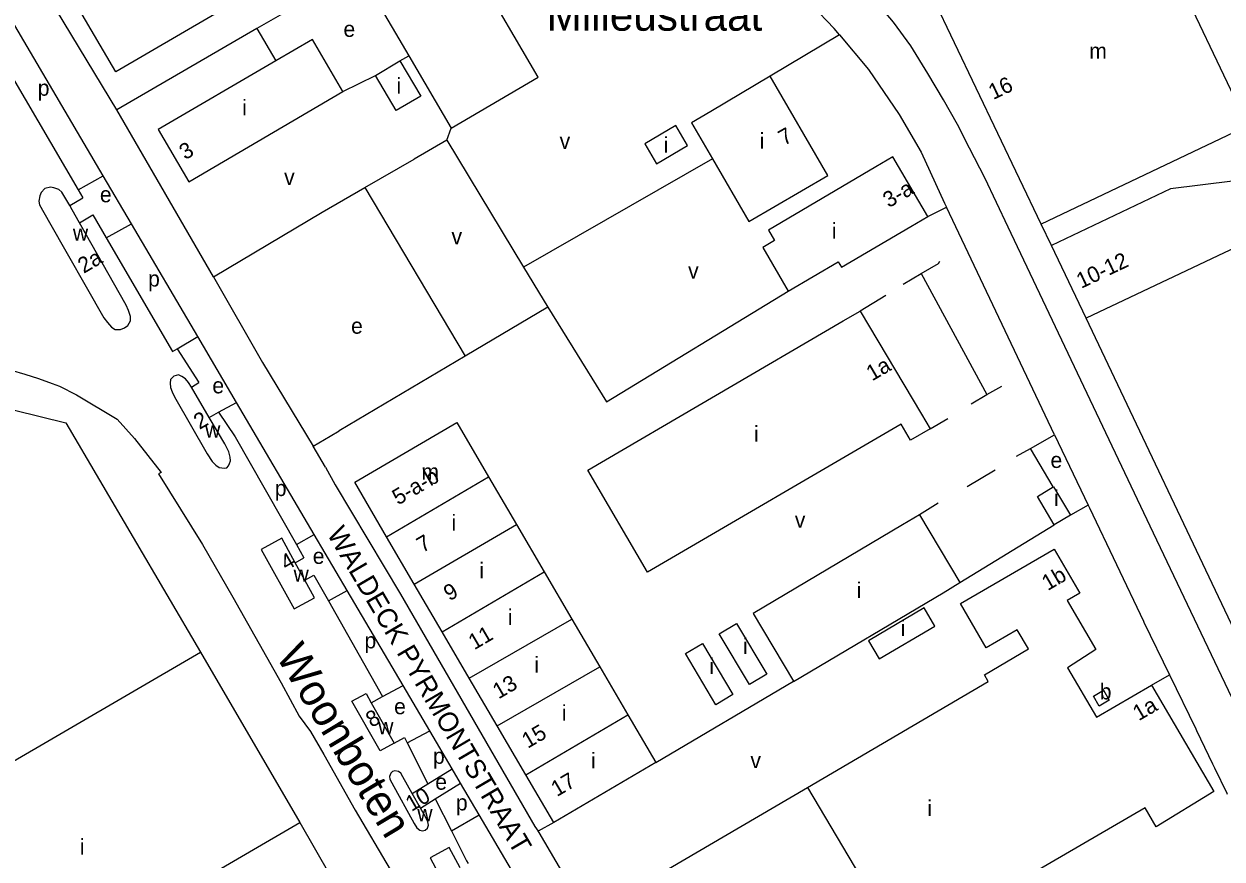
# Model space of a CAD drawing. Extents: x 157699 to 159683, y 381451 to 383293.
# Drawn here: x 159121.6 to 159425.3, y 382524.8 to 382736.7 of the extents above; entities that cross this region are included whole.
import ezdxf

# ---------------------------------------------------------------- set-up
doc = ezdxf.new("R2010")
doc.units = 0
for name, color, linetype in [('BLT_Basislijn', 7, 'Continuous'), ('BLT_Bebouwing', 7, 'Continuous'), ('BLT_Bebouwing_beschrifting', 7, 'Continuous'), ('BLT_Centroide', 7, 'Continuous'), ('BLT_Huisnummer', 7, 'Continuous'), ('BLT_Huisnummer_reeks', 7, 'Continuous'), ('BLT_Onderverdeling_panden', 7, 'Continuous'), ('BLT_Straatnaam', 7, 'Continuous')]:
    doc.layers.add(name, color=color, linetype=linetype)

msp = doc.modelspace()

# ---------------------------------------------------------------- linework, layer by layer
at = {"layer": 'BLT_Basislijn'}
for p, q in [((159081.87, 382786.07), (159135.33, 382694.59)), ((159145.12, 382714.94), (159124.62, 382748.97)), ((159189.49, 382740.66), (159180.65, 382735.54)), ((159180.65, 382735.54), (159145.12, 382714.94)), ((159180.65, 382735.54), (159185.44, 382727.36)), ((159328.36, 382733.92), (159310.76, 382723.44)), ((159216.91, 382727.32), (159219.18, 382728.66)), ((159202.47, 382719.59), (159210.72, 382723.67)), ((159169.62, 382672.57), (159145.12, 382714.94)), ((159228.78, 382707.2), (159229.92, 382710.31)), ((159228.78, 382707.2), (159220.49, 382702.38)), ((159228.78, 382707.2), (159248.23, 382675.04)), ((159208.03, 382695.22), (159220.49, 382702.38)), ((159296.17, 382702.5), (159248.23, 382675.04)), ((159135.33, 382694.59), (159141.7, 382698.15)), ((159135.33, 382694.59), (159136.5, 382692.58)), ((159208.03, 382695.22), (159233.46, 382652.44)), ((159133.19, 382690.63), (159136.5, 382692.58)), ((159350.78, 382687.89), (159355.44, 382690.22)), ((159382.84, 382632.46), (159355.44, 382690.22)), ((159135.67, 382686.29), (159139.02, 382688.26)), ((159139.02, 382688.26), (159142.41, 382682.47)), ((159142.41, 382682.47), (159148.85, 382686)), ((159407.09, 382609.31), (159371.1, 382685.16)), ((159382.07, 382680.52), (159379.52, 382685.92)), ((159142.41, 382682.47), (159159.29, 382653.57)), ((159344.49, 382670.67), (159349.05, 382673.36)), ((159349.05, 382673.36), (159365.71, 382642.67)), ((159340.07, 382667.79), (159333.58, 382663.87)), ((159254.41, 382664.87), (159233.46, 382652.44)), ((159430.88, 382577.83), (159390.88, 382662.04)), ((159160.47, 382654.28), (159165.68, 382657.38)), ((159233.46, 382652.44), (159201.5, 382633.47)), ((159164.08, 382644.56), (159165.89, 382645.71)), ((159365.71, 382642.67), (159369.52, 382644.84)), ((159361.74, 382640.32), (159365.71, 382642.67)), ((159170.95, 382638.2), (159175.49, 382640.69)), ((159168.57, 382636.89), (159170.95, 382638.2)), ((159351.34, 382634.01), (159355.81, 382636.61)), ((159376.77, 382628.98), (159382.84, 382632.46)), ((159382.84, 382632.46), (159391.39, 382614.65)), ((159198.02, 382624.28), (159194.91, 382629.63)), ((159373.21, 382627.02), (159376.77, 382628.98)), ((159382.53, 382619.23), (159376.77, 382628.98)), ((159367.86, 382623.52), (159360.69, 382619.31)), ((159353.39, 382615.09), (159348.65, 382612.2)), ((159391.39, 382614.65), (159386.91, 382612.05)), ((159358.9, 382594.96), (159382.81, 382609.61)), ((159434.7, 382551.26), (159407.09, 382609.31)), ((159190.65, 382604.66), (159195.2, 382607.16)), ((159190.38, 382600), (159192.59, 382601.24)), ((159192.8, 382595.62), (159195.06, 382596.89)), ((159198.77, 382590.34), (159203.55, 382592.97)), ((159405.51, 382584.93), (159412.02, 382571.56)), ((159407.48, 382568.92), (159412.02, 382571.56)), ((159412.02, 382571.56), (159418.71, 382557.83)), ((159212.52, 382566.06), (159217.7, 382568.9)), ((159281.8, 382549.29), (159316.66, 382570)), ((159209.66, 382564.48), (159212.52, 382566.06)), ((159218.78, 382554.28), (159224.46, 382557.4)), ((159215.45, 382554.21), (159218.07, 382555.68)), ((159223.98, 382543.9), (159230.16, 382547.7)), ((159225.86, 382540.15), (159232.28, 382544.1)), ((159220.02, 382541.5), (159223.98, 382543.9)), ((159222.13, 382537.75), (159220.02, 382541.5)), ((159222.13, 382537.75), (159225.86, 382540.15)), ((159229.98, 382531.95), (159237.02, 382536.04)), ((159255.91, 382534.13), (159251.98, 382531.9))]:
    msp.add_line(p, q, dxfattribs=at)
for points in [[(159141.7, 382698.15), (159091.12, 382784.18)], [(159328.36, 382733.92), (159326.98, 382735.56), (159321.31, 382741.52), (159311.44, 382750.26)], [(159371.1, 382685.16), (159365.19, 382697.64), (159361.34, 382705.19), (159358.24, 382711.23), (159354.7, 382717.43), (159350.72, 382724.13), (159346.42, 382731.2), (159342.06, 382737.2), (159335.54, 382744.96), (159330.47, 382750)], [(159328.36, 382733.92), (159335.68, 382725.2), (159343.47, 382713.75), (159349.04, 382704.21), (159354.94, 382691.27), (159355.44, 382690.22)], [(159148.85, 382686), (159141.7, 382698.15)], [(159133.19, 382690.63), (159131.2, 382694.02), (159130.45, 382694.68), (159129.2, 382695.15), (159128.31, 382695.3), (159126.92, 382694.98), (159125.94, 382693.95), (159125.61, 382693.1), (159125.38, 382691.79), (159125.56, 382690.81), (159128.05, 382686.31), (159141.86, 382662.19), (159142.75, 382660.97), (159143.83, 382659.75), (159144.76, 382659.19), (159146.07, 382659.19), (159147.06, 382659.61), (159147.92, 382660.24), (159148.59, 382661.37), (159148.58, 382662.46), (159148.09, 382664.01), (159147.49, 382665.4), (159135.67, 382686.29)], [(159169.62, 382672.57), (159197.21, 382689), (159208.03, 382695.22)], [(159135.67, 382686.29), (159133.8, 382689.59), (159133.19, 382690.63)], [(159165.68, 382657.38), (159148.85, 382686)], [(159248.23, 382675.04), (159253.21, 382666.81), (159254.41, 382664.87)], [(159349.05, 382673.36), (159353.49, 382675.98), (159353.81, 382676.52)], [(159169.62, 382672.57), (159182.07, 382650.78), (159194.91, 382629.63)], [(159254.41, 382664.87), (159269.28, 382640.88), (159315.38, 382668.93)], [(159175.49, 382640.69), (159165.68, 382657.38)], [(159159.29, 382653.57), (159160.47, 382654.28)], [(159160.47, 382654.28), (159165.89, 382645.71)], [(159111.27, 382650.77), (159114.81, 382649.87), (159118.33, 382648.9), (159121.83, 382647.85), (159125.3, 382646.72), (159128.75, 382645.52), (159130.64, 382644.82)], [(159164.08, 382644.56), (159163.3, 382645.73), (159162.52, 382646.67), (159161.63, 382647.29), (159160.77, 382647.65), (159159.61, 382647.36), (159158.77, 382646.49), (159158.65, 382645.57), (159158.74, 382644.49), (159159.17, 382643.35), (159159.79, 382642.08), (159168.05, 382627.62), (159169.32, 382625.74), (159170.27, 382624.78), (159171.11, 382624.19), (159172.4, 382624.01), (159173.05, 382624.1), (159173.45, 382624.62), (159173.71, 382625.18), (159173.94, 382625.83), (159173.85, 382626.84), (159173.5, 382628.15), (159172.5, 382630.18), (159168.57, 382636.89)], [(159130.64, 382644.82), (159134.93, 382642.61), (159145.23, 382636.46), (159149.59, 382631.53), (159156.42, 382622.87), (159155.72, 382622.54), (159166.89, 382604.65), (159174.52, 382591.28)], [(159168.57, 382636.89), (159164.08, 382644.56)], [(159195.2, 382607.16), (159175.49, 382640.69)], [(159170.95, 382638.2), (159175.18, 382631.97), (159190.65, 382604.66)], [(159194.91, 382629.63), (159199.23, 382632.15), (159201.5, 382633.47)], [(159198.02, 382624.28), (159200.53, 382619.74), (159217.09, 382592.02), (159251.08, 382533.1), (159251.98, 382531.9)], [(159391.39, 382614.65), (159391.7, 382613.98), (159405.39, 382585.17), (159405.51, 382584.93)], [(159190.38, 382600), (159186.94, 382606.25), (159181.76, 382603.4), (159190.09, 382588.29), (159195.26, 382591.14), (159192.8, 382595.62)], [(159203.55, 382592.97), (159195.2, 382607.16)], [(159190.65, 382604.66), (159192.59, 382601.24)], [(159192.8, 382595.62), (159190.38, 382600)], [(159195.06, 382596.89), (159198.77, 382590.34)], [(159217.7, 382568.9), (159203.55, 382592.97)], [(159174.52, 382591.28), (159186.77, 382569.5), (159191.38, 382561.09)], [(159198.77, 382590.34), (159212.52, 382566.06)], [(159224.46, 382557.4), (159217.7, 382568.9)], [(159215.45, 382554.21), (159211.87, 382552.26), (159204.75, 382564.91), (159208.32, 382566.85), (159209.66, 382564.48)], [(159209.66, 382564.48), (159215.45, 382554.21)], [(159191.38, 382561.09), (159194.21, 382557.16), (159197.6, 382551.33), (159205.57, 382537.24), (159214.43, 382522.22), (159224.32, 382505.48)], [(159230.16, 382547.7), (159224.46, 382557.4)], [(159418.71, 382557.83), (159418.88, 382557.47), (159422.92, 382548.95), (159423.39, 382547.98)], [(159218.07, 382555.68), (159218.78, 382554.28)], [(159218.78, 382554.28), (159223.98, 382543.9)], [(159220.02, 382541.5), (159217.66, 382545.71), (159217.13, 382546.62), (159216.54, 382547.06), (159215.62, 382547.22), (159215.05, 382547.06), (159214.62, 382546.66), (159214.28, 382545.8), (159214.34, 382545.06), (159214.84, 382544.13), (159220.51, 382533.89), (159221.22, 382532.75), (159221.93, 382532.17), (159222.67, 382531.98), (159223.35, 382532.2), (159223.89, 382532.66), (159224.12, 382533.39), (159223.99, 382534.3), (159223.39, 382535.5), (159222.13, 382537.75)], [(159232.28, 382544.1), (159230.16, 382547.7)], [(159423.39, 382547.98), (159426.53, 382541.52), (159426.63, 382541.3)], [(159237.02, 382536.04), (159232.28, 382544.1)], [(159225.86, 382540.15), (159229.98, 382531.95)], [(159253.41, 382508.18), (159237.02, 382536.04)], [(159229.98, 382531.95), (159233.78, 382524.37), (159234.17, 382523.68)], [(159261.68, 382515.44), (159252.23, 382531.57), (159251.98, 382531.9)], [(159232.2, 382522.57), (159229.41, 382527.8), (159224.57, 382525.15), (159232.37, 382510.53), (159237.21, 382513.18), (159234.56, 382518.16)]]:
    msp.add_lwpolyline(points, dxfattribs=at)
at = {"layer": 'BLT_Bebouwing'}
for p, q in [((159206.41, 382750.47), (159219.18, 382728.66)), ((159379.52, 382685.92), (159351.37, 382744.8)), ((159210.72, 382723.67), (159216.91, 382727.32)), ((159219.18, 382728.66), (159229.92, 382710.31)), ((159310.76, 382723.44), (159295.71, 382714.53)), ((159341.88, 382703), (159337.57, 382700.46)), ((159350.78, 382687.89), (159341.88, 382703)), ((159337.57, 382700.46), (159310.33, 382684.43)), ((159474.33, 382701.74), (159390.88, 382662.04)), ((159310.33, 382684.43), (159311.89, 382681.76)), ((159311.89, 382681.76), (159308.88, 382679.98)), ((159308.88, 382679.98), (159315.38, 382668.93)), ((159390.88, 382662.04), (159382.07, 382680.52)), ((159333.58, 382663.87), (159349.17, 382637.72)), ((159231.31, 382635.62), (159239.39, 382621.81)), ((159239.39, 382621.81), (159246.44, 382609.75)), ((159348.65, 382612.2), (159358.9, 382594.96)), ((159386.91, 382612.05), (159382.81, 382609.61)), ((159246.44, 382609.75), (159253.51, 382597.67)), ((159220.56, 382594.54), (159213.52, 382606.6)), ((159253.51, 382597.67), (159260.5, 382585.72)), ((159227.63, 382582.45), (159220.56, 382594.54)), ((159260.5, 382585.72), (159267.58, 382573.61)), ((159234.46, 382570.76), (159227.63, 382582.45)), ((159166.39, 382577.3), (159191.55, 382534.13)), ((159267.58, 382573.61), (159274.7, 382561.44)), ((159241.58, 382558.6), (159234.46, 382570.76)), ((159407.48, 382568.92), (159423.24, 382542.01)), ((159274.7, 382561.44), (159281.8, 382549.29)), ((159248.82, 382546.2), (159241.58, 382558.6)), ((159281.8, 382549.29), (159255.91, 382534.13)), ((159255.91, 382534.13), (159248.82, 382546.2))]:
    msp.add_line(p, q, dxfattribs=at)
for points in [[(159229.92, 382710.31), (159251.98, 382723.22), (159236.3, 382750), (159219.86, 382778.09), (159215.55, 382775.56), (159197.8, 382765.18), (159206.41, 382750.47)], [(159403.79, 382769.82), (159431.91, 382710.87)], [(159133.21, 382744.52), (159166.08, 382763.7), (159177.71, 382743.78), (159144.85, 382724.61), (159133.21, 382744.52)], [(159202.47, 382719.59), (159194.73, 382732.8), (159185.44, 382727.36)], [(159185.44, 382727.36), (159155.66, 382709.91), (159163.4, 382696.7)], [(159216.91, 382727.32), (159222.18, 382718.36), (159215.99, 382714.72), (159210.72, 382723.67)], [(159296.17, 382702.5), (159305.37, 382686.62), (159325.39, 382698.28), (159310.76, 382723.44)], [(159163.4, 382696.7), (159202.47, 382719.59)], [(159295.71, 382714.53), (159290.86, 382711.66), (159296.17, 382702.5)], [(159446.99, 382715.3), (159453.07, 382703.17), (159443.72, 382698.76), (159412.28, 382694.86), (159382.07, 382680.52)], [(159431.91, 382710.87), (159379.52, 382685.92)], [(159315.38, 382668.93), (159328.04, 382676.38), (159328.86, 382674.99), (159346.47, 382685.35), (159350.78, 382687.89)], [(159351.34, 382634.01), (159346.35, 382631.1), (159343.99, 382635.13), (159279.65, 382597.58), (159264.53, 382623.51), (159329.26, 382661.35), (159333.58, 382663.87)], [(159099.29, 382643.64), (159132.19, 382635.51), (159166.39, 382577.3)], [(159213.52, 382606.6), (159205.44, 382620.44), (159231.31, 382635.62)], [(159349.17, 382637.72), (159351.34, 382634.01)], [(159382.81, 382609.61), (159378.51, 382616.84), (159382.53, 382619.23)], [(159382.53, 382619.23), (159382.62, 382619.28), (159386.91, 382612.05)], [(159348.65, 382612.2), (159344.36, 382609.64), (159306.48, 382587.12), (159316.66, 382570)], [(159365.57, 382578.46), (159359.04, 382589.69), (159382.74, 382603.48), (159389.26, 382592.25), (159386.1, 382590.42), (159393.32, 382577.97), (159386.14, 382573.37), (159393.53, 382560.79), (159407.48, 382568.92)], [(159316.66, 382570), (159316.72, 382569.89), (159354.6, 382592.4), (159358.9, 382594.96)], [(159297.88, 382582), (159302.27, 382584.61), (159309.9, 382571.77), (159305.5, 382569.16), (159297.88, 382582)], [(159366.07, 382569.88), (159365.09, 382571.56), (159376.25, 382578.18), (159373.39, 382582.99), (159365.57, 382578.46)], [(159289.33, 382576.95), (159293.65, 382579.52), (159301.35, 382566.57), (159297.03, 382564), (159289.33, 382576.95)], [(159320.28, 382542.95), (159366.07, 382569.88)], [(159394.2, 382563.64), (159392.71, 382566.2), (159395.26, 382567.69), (159396.75, 382565.13), (159394.2, 382563.64)], [(159303.35, 382533.07), (159320.28, 382542.95)], [(159423.24, 382542.01), (159408.67, 382532.99), (159405.86, 382537.84), (159357.21, 382509.45)], [(159191.55, 382534.13), (159211.08, 382500.02), (159211.48, 382499.28)], [(159278.72, 382515.21), (159277.2, 382517.82), (159281.52, 382520.34), (159303.35, 382533.07)]]:
    msp.add_lwpolyline(points, dxfattribs=at)
for points in [[(159279.01, 382706.28), (159281.99, 382701.24), (159289.81, 382705.88), (159286.82, 382710.91)], [(159349.79, 382588.53), (159335.67, 382580.2), (159338.37, 382575.62), (159352.49, 382583.94)]]:
    msp.add_lwpolyline(points, close=True, dxfattribs=at)
at = {"layer": 'BLT_Onderverdeling_panden'}
for p, q in [((159213.52, 382606.6), (159239.39, 382621.81)), ((159220.56, 382594.54), (159246.44, 382609.75)), ((159227.63, 382582.45), (159253.51, 382597.67)), ((159234.46, 382570.76), (159260.5, 382585.72)), ((159081.88, 382528.05), (159166.39, 382577.3)), ((159241.58, 382558.6), (159267.58, 382573.61)), ((159248.82, 382546.2), (159274.7, 382561.44)), ((159320.28, 382542.95), (159339.1, 382511.27)), ((159107.07, 382484.9), (159191.55, 382534.13))]:
    msp.add_line(p, q, dxfattribs=at)

# ---------------------------------------------------------------- texts
at = {"layer": 'BLT_Bebouwing_beschrifting'}
for s, rotation, p in [('Milieustraat', 359.9999, (159254.09, 382735)), ('Woonboten', 301.028, (159185.31, 382576.42))]:
    msp.add_text(s, height=8, rotation=rotation, dxfattribs=at).set_placement(p)
at = {"layer": 'BLT_Centroide'}
for s, p in [('e', (159202.6, 382733.44)), ('m', (159391.67, 382727.88)), ('p', (159125.09, 382718.5)), ('i', (159216.04, 382719.06)), ('i', (159176.91, 382713.5)), ('i', (159283.76, 382704.03)), ('i', (159308.12, 382705.05)), ('v', (159257.4, 382705.02)), ('v', (159187.55, 382695.88)), ('e', (159140.85, 382691.47)), ('w', (159134, 382681.71)), ('v', (159229.99, 382680.82)), ('i', (159326.41, 382682.25)), ('v', (159289.97, 382672.11)), ('p', (159153.07, 382670.09)), ('e', (159204.53, 382658.12)), ('e', (159169.36, 382642.99)), ('w', (159167.52, 382631.78)), ('i', (159306.66, 382630.72)), ('e', (159381.85, 382624.06)), ('m', (159222.35, 382621.12)), ('p', (159185.19, 382616.93)), ('i', (159382.72, 382614.45)), ('i', (159229.98, 382608.19)), ('v', (159317.03, 382608.9)), ('e', (159194.81, 382599.72)), ('i', (159237.03, 382596.09)), ('w', (159189.95, 382595.22)), ('i', (159332.7, 382591.03)), ('i', (159244.25, 382584.22)), ('i', (159343.84, 382581.39)), ('p', (159207.93, 382578.28)), ('i', (159303.89, 382576.88)), ('i', (159250.98, 382572.16)), ('i', (159295.34, 382571.77)), ('b', (159394.34, 382565.33)), ('e', (159215.44, 382561.57)), ('i', (159257.96, 382559.91)), ('w', (159211.4, 382556.49)), ('p', (159225.3, 382548.99)), ('i', (159265.33, 382547.81)), ('v', (159305.77, 382547.89)), ('e', (159225.87, 382542.42)), ('p', (159231.1, 382537.17)), ('i', (159350.64, 382535.76)), ('w', (159221.32, 382534.42)), ('i', (159135.77, 382525.98))]:
    msp.add_text(s, height=4, dxfattribs=at).set_placement(p)
at = {"layer": 'BLT_Huisnummer'}
for s, rotation, p in [('16', 25.3509, (159367.32, 382717.4)), ('7', 29.553, (159314.31, 382705.73)), ('3', 30.344, (159162.46, 382702.11)), ('2a', 30.6895, (159136.75, 382673.29)), ('1a', 30.2718, (159336.62, 382646.01)), ('2', 30.1314, (159166.11, 382633.71)), ('7', 30.3193, (159222.64, 382602.43)), ('4', 30.1314, (159188.1, 382597.91)), ('9', 30.3193, (159229.48, 382590.19)), ('11', 30.3193, (159235.76, 382577.79)), ('13', 30.3193, (159241.92, 382565.32)), ('8', 30.1314, (159209.74, 382558.08)), ('15', 30.3193, (159249.32, 382552.79)), ('17', 30.3193, (159256.71, 382540.54)), ('10', 30.1314, (159219.83, 382536.77))]:
    msp.add_text(s, height=4, rotation=rotation, dxfattribs=at).set_placement(p)
at = {"layer": 'BLT_Huisnummer_reeks'}
for s, rotation, p in [('3-a', 30.4761, (159340.85, 382689.95)), ('10-12', 25.3503, (159389.61, 382669.49)), ('5-a-b', 30.3193, (159216.44, 382614.52)), ('1b', 30.3009, (159381.13, 382592.8)), ('1a', 30.3009, (159404.2, 382559.77))]:
    msp.add_text(s, height=4, rotation=rotation, dxfattribs=at).set_placement(p)
at = {"layer": 'BLT_Straatnaam'}
msp.add_text('WALDECK PYRMONTSTRAAT', height=5, rotation=300.3946, dxfattribs=at).set_placement((159198.29, 382607.38))

doc.saveas('drawing.dxf')
